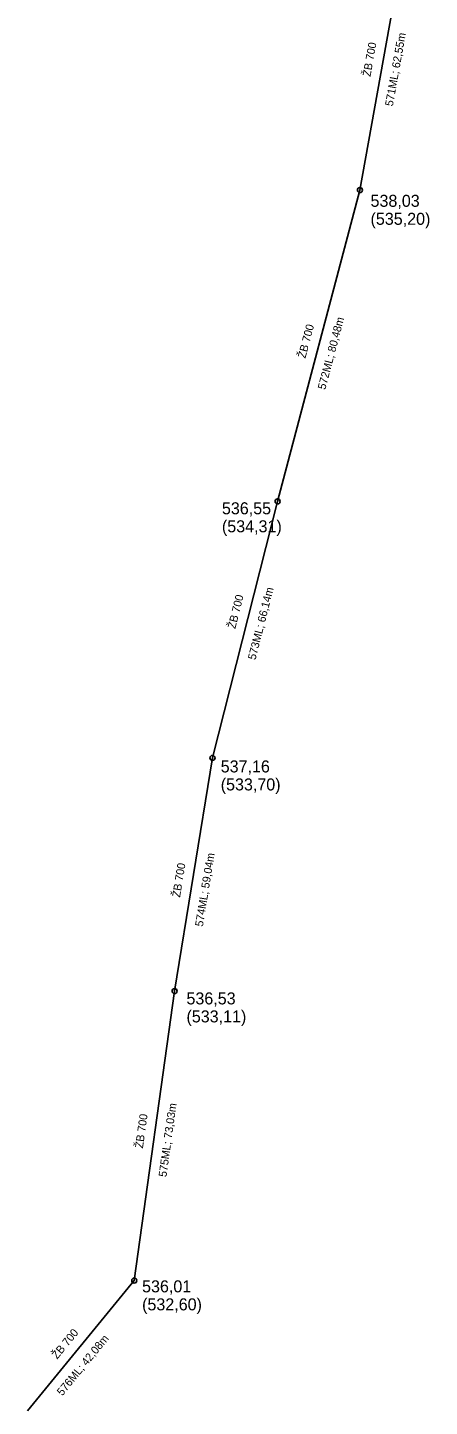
# Model space of a CAD drawing. Extents: x -867696 to -865033, y -1042522 to -1039817.
# Drawn here: x -866012.4 to -865912.1, y -1041184.7 to -1040840.1 of the extents above; entities that cross this region are included whole.
import ezdxf

# ---------------------------------------------------------------- set-up
doc = ezdxf.new("R2010")
doc.units = 0
for name, color, linetype in [('KN - jednotna', 7, 'Continuous'), ('KN - popis material', 7, 'Continuous'), ('KN - popis ostatni', 7, 'Continuous'), ('KN - popis usek delka', 7, 'Continuous'), ('KN - sachta komora', 7, 'Continuous'), ('Level 1', 7, 'Continuous')]:
    doc.layers.add(name, color=color, linetype=linetype)

# ---------------------------------------------------------------- blocks, each defined once
blk = doc.blocks.new('100.M')
at = {"layer": 'Level 1'}
blk.add_circle((0, 0), 1.27, dxfattribs=at)

msp = doc.modelspace()

# ---------------------------------------------------------------- linework, layer by layer
at = {"layer": 'KN - jednotna'}
for points in [[(-865918.379, -1040819.098), (-865929.417, -1040880.668)], [(-865929.417, -1040880.668), (-865949.958, -1040958.478)], [(-865949.958, -1040958.478), (-865966.218, -1041022.589)], [(-865966.218, -1041022.589), (-865975.689, -1041080.867)], [(-865975.689, -1041080.867), (-865985.758, -1041153.198)], [(-865985.758, -1041153.198), (-866012.377, -1041185.788)]]:
    msp.add_lwpolyline(points, dxfattribs=at)

# ---------------------------------------------------------------- block references
at = {"layer": 'KN - sachta komora'}
for p, xscale, yscale, rotation in [((-865929.417, -1040880.668), 0.5000000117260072, 0.5000000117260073, -101.99999938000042), ((-865949.958, -1040958.478), 0.5000000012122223, 0.5000000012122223, -104.00000032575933), ((-865966.218, -1041022.589), 0.499999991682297, 0.4999999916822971, -101.0000002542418), ((-865975.689, -1041080.867), 0.49999999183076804, 0.49999999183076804, -98.00000038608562), ((-865985.758, -1041153.198), 0.5000000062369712, 0.500000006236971, -112.99999954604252)]:
    msp.add_blockref('100.M', p, dxfattribs=dict(at, xscale=xscale, yscale=yscale, rotation=rotation))

# ---------------------------------------------------------------- texts
at = {"layer": 'KN - popis material'}
for rotation, p in [(79.84, (-865926.794, -1040852.441)), (75.21, (-865943.037, -1040922.858)), (75.77, (-865960.541, -1040990.445)), (80.77, (-865974.328, -1041057.533)), (82.07, (-865983.592, -1041120.23)), (50.76, (-866005.003, -1041172.966))]:
    msp.add_text('ŽB 700', height=2, rotation=rotation, dxfattribs=at).set_placement(p)
at = {"layer": 'KN - popis ostatni'}
for s, p in [('538,03 ', (-865926.767, -1040884.868)), ('(535,20)', (-865926.767, -1040889.368)), ('536,55 ', (-865963.868, -1040961.708)), ('(534,31)', (-865963.868, -1040966.208)), ('537,16 ', (-865964.168, -1041026.219)), ('(533,70)', (-865964.168, -1041030.719)), ('536,53 ', (-865972.719, -1041084.187)), ('(533,11)', (-865972.719, -1041088.687)), ('536,01 ', (-865983.798, -1041156.148)), ('(532,60)', (-865983.798, -1041160.648))]:
    msp.add_text(s, height=3, dxfattribs=at).set_placement(p)
at = {"layer": 'KN - popis usek delka'}
for s, rotation, p in [('571ML; 62,55m', 79.84, (-865921.212, -1040859.842)), ('572ML; 80,48m', 75.21, (-865938.07, -1040930.685)), ('573ML; 66,14m', 75.77, (-865955.499, -1040998.223)), ('574ML; 59,04m', 80.77, (-865968.627, -1041064.842)), ('575ML; 73,03m', 82.07, (-865977.726, -1041127.407)), ('576ML; 42,08m', 50.76, (-866003.722, -1041182.147))]:
    msp.add_text(s, height=1.99999, rotation=rotation, dxfattribs=at).set_placement(p)

doc.saveas('drawing.dxf')
